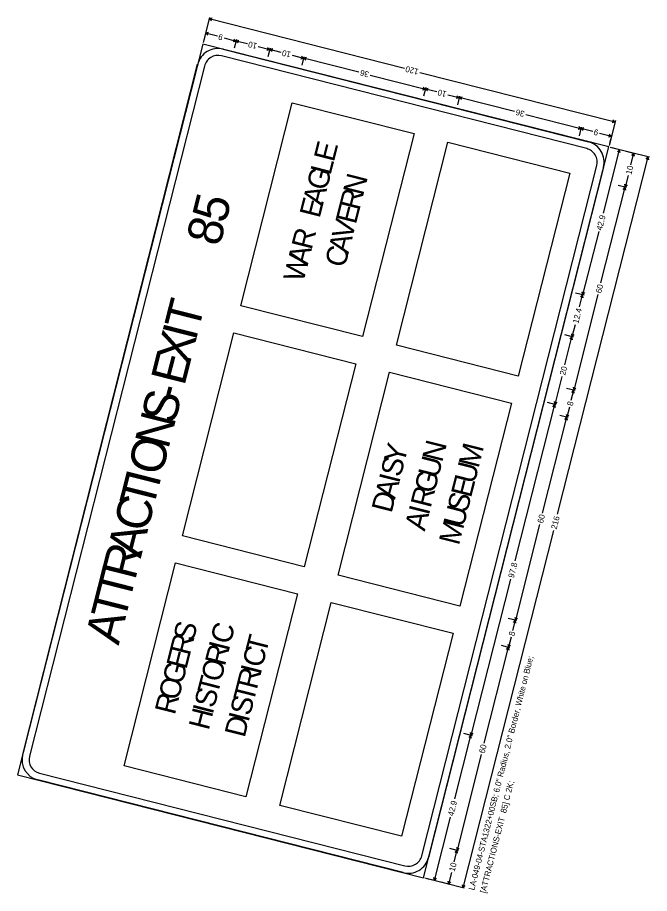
# Model space of a CAD drawing. Extents: x 670257 to 671518, y 737783 to 738188.
# Drawn here: x 670990.48 to 671016.9, y 737940.95 to 737977.55 of the extents above; entities that cross this region are included whole.
import ezdxf

# ---------------------------------------------------------------- set-up
doc = ezdxf.new("R2010")
doc.units = 0
doc.layers.add('R_SIGN', color=7, linetype='Continuous')

msp = doc.modelspace()

# ---------------------------------------------------------------- linework, layer by layer
at = {"layer": 'R_SIGN'}
for p, q in [((670998.509, 737977.55), (670998.244, 737976.503)), ((670998.615, 737977.517), (670998.494, 737977.49)), ((671006.654, 737975.421), (670998.494, 737977.49)), ((670998.587, 737977.41), (670998.494, 737977.49)), ((670998.357, 737976.952), (670998.266, 737976.593)), ((670998.463, 737976.918), (670998.342, 737976.892)), ((670998.836, 737976.767), (670998.342, 737976.892)), ((670998.436, 737976.811), (670998.342, 737976.892)), ((670999.12, 737976.695), (670999.615, 737976.569)), ((670999.494, 737976.543), (670999.615, 737976.569)), ((670999.521, 737976.65), (670999.615, 737976.569)), ((670999.63, 737976.629), (670999.539, 737976.27)), ((670999.735, 737976.596), (670999.615, 737976.569)), ((671000.095, 737976.447), (670999.615, 737976.569)), ((670999.708, 737976.489), (670999.615, 737976.569)), ((671000.547, 737976.333), (671001.028, 737976.211)), ((671000.908, 737976.184), (671001.028, 737976.211)), ((671000.935, 737976.291), (671001.028, 737976.211)), ((671001.043, 737976.271), (671000.952, 737975.912)), ((671001.149, 737976.237), (671001.028, 737976.211)), ((671001.509, 737976.089), (671001.028, 737976.211)), ((671001.122, 737976.13), (671001.028, 737976.211)), ((671001.961, 737975.974), (671002.442, 737975.852)), ((671002.321, 737975.826), (671002.442, 737975.852)), ((671002.348, 737975.933), (671002.442, 737975.852)), ((671002.457, 737975.912), (671002.366, 737975.553)), ((671002.562, 737975.879), (671002.442, 737975.852)), ((671004.748, 737975.267), (671002.442, 737975.852)), ((671002.535, 737975.772), (671002.442, 737975.852)), ((671005.224, 737975.146), (671007.531, 737974.562)), ((671007.297, 737975.257), (671015.457, 737973.188)), ((671007.41, 737974.535), (671007.531, 737974.562)), ((671007.437, 737974.642), (671007.531, 737974.562)), ((671007.546, 737974.621), (671007.455, 737974.262)), ((671007.651, 737974.588), (671007.531, 737974.562)), ((671008.011, 737974.44), (671007.531, 737974.562)), ((671007.624, 737974.481), (671007.531, 737974.562)), ((671008.463, 737974.325), (671008.944, 737974.203)), ((670999.818, 737965.508), (671001.969, 737973.99)), ((671001.969, 737973.99), (671007.058, 737972.699)), ((671008.824, 737974.177), (671008.944, 737974.203)), ((671008.851, 737974.284), (671008.944, 737974.203)), ((671008.959, 737974.263), (671008.868, 737973.904)), ((671009.065, 737974.229), (671008.944, 737974.203)), ((671011.25, 737973.618), (671008.944, 737974.203)), ((671009.038, 737974.122), (671008.944, 737974.203)), ((671011.727, 737973.497), (671014.033, 737972.912)), ((671015.472, 737973.248), (671015.207, 737972.201)), ((671015.364, 737973.269), (671015.457, 737973.188)), ((671013.912, 737972.886), (671014.033, 737972.912)), ((671013.94, 737972.993), (671014.033, 737972.912)), ((671014.048, 737972.972), (671013.957, 737972.613)), ((671014.048, 737972.972), (671013.957, 737972.613)), ((671014.154, 737972.939), (671014.033, 737972.912)), ((671014.527, 737972.787), (671014.033, 737972.912)), ((671014.126, 737972.832), (671014.033, 737972.912)), ((671015.336, 737973.162), (671015.457, 737973.188)), ((671007.058, 737972.699), (671004.907, 737964.218)), ((671014.811, 737972.715), (671015.305, 737972.59)), ((671015.185, 737972.563), (671015.305, 737972.59)), ((671015.212, 737972.67), (671015.305, 737972.59)), ((671015.32, 737972.65), (671015.229, 737972.291)), ((671006.321, 737963.859), (671008.472, 737972.341)), ((671008.472, 737972.341), (671013.561, 737971.05)), ((671016.897, 737971.709), (671015.251, 737972.126)), ((671014.969, 737969.382), (671015.64, 737972.027)), ((671015.7, 737972.012), (671015.341, 737972.103)), ((671015.56, 737971.934), (671015.64, 737972.027)), ((671015.667, 737971.907), (671015.64, 737972.027)), ((671016.298, 737971.86), (671015.939, 737971.951)), ((671016.116, 737971.395), (671016.238, 737971.876)), ((671016.158, 737971.782), (671016.238, 737971.876)), ((671016.265, 737971.755), (671016.238, 737971.876)), ((671013.05, 737956.794), (671016.837, 737971.724)), ((671016.756, 737971.63), (671016.837, 737971.724)), ((671016.863, 737971.603), (671016.837, 737971.724)), ((671013.561, 737971.05), (671011.41, 737962.569)), ((671016.002, 737970.943), (671015.88, 737970.462)), ((671014.865, 737966.459), (671015.88, 737970.462)), ((671015.94, 737970.447), (671015.581, 737970.538)), ((671015.94, 737970.447), (671015.581, 737970.538)), ((671015.799, 737970.368), (671015.88, 737970.462)), ((671015.854, 737970.583), (671015.88, 737970.462)), ((671015.961, 737970.555), (671015.88, 737970.462)), ((671015.906, 737970.341), (671015.88, 737970.462)), ((671014.773, 737968.608), (671014.102, 737965.963)), ((671014.744, 737965.983), (671013.729, 737961.98)), ((671014.162, 737965.948), (671013.803, 737966.039)), ((671014.162, 737965.948), (671013.803, 737966.039)), ((671013.973, 737965.456), (671014.102, 737965.963)), ((671014.022, 737965.87), (671014.102, 737965.963)), ((671014.076, 737966.084), (671014.102, 737965.963)), ((671014.183, 737966.056), (671014.102, 737965.963)), ((671014.129, 737965.842), (671014.102, 737965.963)), ((671004.907, 737964.218), (670999.818, 737965.508)), ((671013.786, 737964.717), (671013.658, 737964.21)), ((670997.38, 737955.896), (670999.531, 737964.378)), ((670999.531, 737964.378), (671004.62, 737963.087)), ((671013.717, 737964.195), (671013.358, 737964.286)), ((671013.36, 737963.036), (671013.658, 737964.21)), ((671013.577, 737964.117), (671013.658, 737964.21)), ((671013.631, 737964.331), (671013.658, 737964.21)), ((671013.738, 737964.304), (671013.658, 737964.21)), ((671013.684, 737964.09), (671013.658, 737964.21)), ((671011.41, 737962.569), (671006.321, 737963.859)), ((671004.62, 737963.087), (671002.469, 737954.606)), ((671003.883, 737954.247), (671006.034, 737962.728)), ((671006.034, 737962.728), (671011.123, 737961.438)), ((671013.238, 737962.558), (671012.94, 737961.383)), ((671013.789, 737961.965), (671013.43, 737962.056)), ((671013.621, 737961.558), (671013.729, 737961.98)), ((671013.648, 737961.887), (671013.729, 737961.98)), ((671013.702, 737962.101), (671013.729, 737961.98)), ((671013.809, 737962.074), (671013.729, 737961.98)), ((671013.755, 737961.86), (671013.729, 737961.98)), ((671012.914, 737961.504), (671012.94, 737961.383)), ((671011.123, 737961.438), (671008.972, 737952.956)), ((671011.284, 737954.852), (671012.94, 737961.383)), ((671013, 737961.368), (671012.641, 737961.459)), ((671012.86, 737961.29), (671012.94, 737961.383)), ((671013.021, 737961.476), (671012.94, 737961.383)), ((671012.967, 737961.262), (671012.94, 737961.383)), ((671013.549, 737961.273), (671013.442, 737960.85)), ((671012.427, 737956.847), (671013.442, 737960.85)), ((671013.502, 737960.834), (671013.143, 737960.925)), ((671013.361, 737960.756), (671013.442, 737960.85)), ((671013.416, 737960.97), (671013.442, 737960.85)), ((671013.523, 737960.943), (671013.442, 737960.85)), ((671013.468, 737960.729), (671013.442, 737960.85)), ((671012.879, 737956.12), (671009.093, 737941.19)), ((671012.306, 737956.371), (671011.291, 737952.368)), ((671002.469, 737954.606), (670997.38, 737955.896)), ((670994.942, 737946.284), (670997.094, 737954.765)), ((670997.094, 737954.765), (671002.182, 737953.475)), ((671008.972, 737952.956), (671003.883, 737954.247)), ((671011.091, 737954.089), (671009.434, 737947.558)), ((671002.182, 737953.475), (671000.031, 737944.993)), ((671001.445, 737944.635), (671003.596, 737953.116)), ((671003.596, 737953.116), (671008.685, 737951.825)), ((671011.351, 737952.353), (671010.992, 737952.444)), ((671011.184, 737951.945), (671011.291, 737952.368)), ((671011.21, 737952.275), (671011.291, 737952.368)), ((671011.265, 737952.489), (671011.291, 737952.368)), ((671011.372, 737952.462), (671011.291, 737952.368)), ((671011.317, 737952.248), (671011.291, 737952.368)), ((671008.685, 737951.825), (671006.534, 737943.344)), ((671011.111, 737951.66), (671011.004, 737951.237)), ((671011.064, 737951.222), (671010.705, 737951.313)), ((671010.978, 737951.358), (671011.004, 737951.237)), ((671011.085, 737951.331), (671011.004, 737951.237)), ((671009.989, 737947.234), (671011.004, 737951.237)), ((671010.923, 737951.144), (671011.004, 737951.237)), ((671011.03, 737951.117), (671011.004, 737951.237)), ((671009.494, 737947.543), (671009.135, 737947.634)), ((671009.408, 737947.679), (671009.434, 737947.558)), ((671009.515, 737947.652), (671009.434, 737947.558)), ((671008.763, 737944.913), (671009.434, 737947.558)), ((671009.354, 737947.465), (671009.434, 737947.558)), ((671009.461, 737947.438), (671009.434, 737947.558)), ((671009.868, 737946.759), (671008.853, 737942.756)), ((671000.031, 737944.993), (670994.942, 737946.284)), ((671006.534, 737943.344), (671001.445, 737944.635)), ((671008.567, 737944.139), (671007.896, 737941.494)), ((671008.827, 737942.876), (671008.853, 737942.756)), ((671008.934, 737942.849), (671008.853, 737942.756)), ((671008.913, 737942.741), (671008.554, 737942.832)), ((671008.731, 737942.275), (671008.853, 737942.756)), ((671008.772, 737942.662), (671008.853, 737942.756)), ((671008.879, 737942.635), (671008.853, 737942.756)), ((671008.616, 737941.823), (671008.494, 737941.342)), ((671009.153, 737941.175), (671007.507, 737941.593)), ((671007.956, 737941.479), (671007.597, 737941.57)), ((671007.87, 737941.615), (671007.896, 737941.494)), ((671007.977, 737941.587), (671007.896, 737941.494)), ((671008.554, 737941.327), (671008.195, 737941.418)), ((671008.468, 737941.463), (671008.494, 737941.342)), ((671008.575, 737941.436), (671008.494, 737941.342)), ((671009.066, 737941.311), (671009.093, 737941.19)), ((671009.173, 737941.284), (671009.093, 737941.19))]:
    msp.add_line(p, q, dxfattribs=at)
for points in [[(671007.448, 737941.608), (671015.191, 737972.141), (670998.229, 737976.443), (670990.485, 737945.91), (671007.448, 737941.608), (671007.448, 737941.608)], [(670999.077, 737976.228), (671014.343, 737972.356)], [(671014.272, 737972.073), (670999.005, 737975.945)], [(670990.7, 737946.758), (670998.013, 737975.595)], [(670998.296, 737975.523), (670990.982, 737946.686)], [(671007.38, 737942.528), (671014.694, 737971.365)], [(671014.976, 737971.293), (671007.663, 737942.456)], [(670991.404, 737945.978), (671006.671, 737942.106)], [(671006.599, 737941.823), (670991.333, 737945.695)]]:
    msp.add_lwpolyline(points, dxfattribs=at)
for centre, radius, start, end in [((670998.862, 737975.38), 0.875, 75.7686, 165.7688), ((670998.862, 737975.38), 0.583, 75.7686, 165.7688), ((671014.128, 737971.508), 0.875, 345.7686, 75.7688), ((671014.128, 737971.508), 0.583, 345.7686, 75.7688), ((670991.548, 737946.543), 0.875, 165.7688, 255.7684), ((670991.548, 737946.543), 0.583, 165.7688, 255.7684), ((671006.814, 737942.671), 0.583, 255.7684, 345.7686), ((671006.814, 737942.671), 0.875, 255.7684, 345.7686)]:
    msp.add_arc(centre, radius, start, end, dxfattribs=at)

# ---------------------------------------------------------------- texts
for s, height, rotation, p in [('9', 0.247, 165.7688, (670999.091, 737976.829)), ('10', 0.2469, 165.7688, (671000.518, 737976.468)), ('10', 0.2469, 165.7688, (671001.931, 737976.109)), ('120', 0.2469, 165.7688, (671007.268, 737975.392)), ('36', 0.2469, 165.7688, (671005.195, 737975.281)), ('10', 0.2469, 165.7688, (671008.434, 737974.46)), ('36', 0.2469, 165.7688, (671011.697, 737973.632)), ('9', 0.247, 165.7688, (671014.782, 737972.85)), ('E', 0.875, 75.7686, (671003.703, 737971.483)), ('L', 0.875, 75.7686, (671003.563, 737970.932)), ('G', 0.875, 75.7686, (671003.4, 737970.287)), ('N', 0.875, 75.7686, (671004.926, 737970.076)), ('10', 0.2469, 75.7686, (671016.137, 737970.972)), ('A', 0.875, 75.7686, (671003.236, 737969.643)), ('R', 0.875, 75.7686, (671004.769, 737969.457)), ('5', 1.458, 75.7686, (670999.176, 737968.906)), ('E', 0.875, 75.7686, (671003.107, 737969.134)), ('E', 0.875, 75.7686, (671004.623, 737968.88)), ('8', 1.458, 75.7686, (670998.932, 737967.945)), ('V', 0.875, 75.7686, (671004.459, 737968.236)), ('42.9', 0.2469, 75.7686, (671014.908, 737968.638)), ('R', 0.875, 75.7686, (671002.772, 737967.811)), ('A', 0.875, 75.7686, (671004.309, 737967.642)), ('W', 0.875, 75.7686, (671002.428, 737966.454)), ('A', 0.875, 75.7686, (671002.604, 737967.149)), ('C', 0.875, 75.7686, (671004.162, 737967.065)), ('60', 0.2469, 75.7686, (671014.879, 737966.013)), ('T', 1.458, 75.7686, (670998.032, 737964.397)), ('12.4', 0.2469, 75.7686, (671013.921, 737964.747)), ('X', 1.458, 75.7686, (670997.67, 737962.969)), ('I', 1.458, 75.7686, (670997.931, 737964.001)), ('E', 1.458, 75.7686, (670997.455, 737962.121)), ('20', 0.2469, 75.7686, (671013.373, 737962.587)), ('S', 1.458, 75.7686, (670997.046, 737960.51)), ('-', 1.458, 75.7686, (670997.279, 737961.428)), ('8', 0.247, 75.7686, (671013.684, 737961.302)), ('N', 1.458, 75.7686, (670996.784, 737959.478)), ('O', 1.458, 75.7686, (670996.501, 737958.361)), ('Y', 0.875, 75.7686, (671006.634, 737958.866)), ('N', 0.875, 75.7686, (671008.231, 737958.935)), ('M', 0.875, 75.7686, (671009.749, 737958.69)), ('S', 0.875, 75.7686, (671006.494, 737958.315)), ('U', 0.875, 75.7686, (671008.063, 737958.273)), ('U', 0.875, 75.7686, (671009.581, 737958.028)), ('I', 1.458, 75.7686, (670996.379, 737957.88)), ('G', 0.875, 75.7686, (671007.9, 737957.629)), ('T', 1.458, 75.7686, (670996.146, 737956.961)), ('I', 0.875, 75.7686, (671006.428, 737958.052)), ('E', 0.875, 75.7686, (671009.435, 737957.452)), ('A', 0.875, 75.7686, (671006.26, 737957.39)), ('R', 0.875, 75.7686, (671007.747, 737957.027)), ('C', 1.458, 75.7686, (670995.902, 737956)), ('D', 0.875, 75.7686, (671006.114, 737956.814)), ('S', 0.875, 75.7686, (671009.278, 737956.833)), ('I', 0.875, 75.7686, (671007.67, 737956.721)), ('U', 0.875, 75.7686, (671009.121, 737956.213)), ('A', 0.875, 75.7686, (671007.502, 737956.06)), ('60', 0.2469, 75.7686, (671012.441, 737956.401)), ('M', 0.875, 75.7686, (671008.931, 737955.467)), ('216', 0.2469, 75.7686, (671013.014, 737956.15)), ('A', 1.458, 75.7686, (670995.63, 737954.926)), ('R', 1.458, 75.7686, (670995.397, 737954.007)), ('T', 1.458, 75.7686, (670995.164, 737953.088)), ('97.8', 0.2469, 75.7686, (671011.225, 737954.118)), ('T', 1.458, 75.7686, (670994.959, 737952.283)), ('A', 1.458, 75.7686, (670994.708, 737951.293)), ('S', 0.875, 75.7686, (670997.829, 737951.437)), ('C', 0.875, 75.7686, (670999.381, 737951.328)), ('R', 0.875, 75.7686, (670997.683, 737950.861)), ('T', 0.875, 75.7686, (671000.859, 737950.926)), ('8', 0.247, 75.7686, (671011.246, 737951.69)), ('R', 0.875, 75.7686, (670999.151, 737950.421)), ('I', 0.875, 75.7686, (670999.308, 737951.04)), ('C', 0.875, 75.7686, (671000.713, 737950.349)), ('E', 0.875, 75.7686, (670997.537, 737950.284)), ('G', 0.875, 75.7686, (670997.373, 737949.639)), ('O', 0.875, 75.7686, (670998.981, 737949.75)), ('LA-049-04-STA1322+00SB; 6.0" Radius, 2.0" Border, White on Blue; ', 0.24688, 75.7686, (671009.571, 737941.069)), ('R', 0.875, 75.7686, (671000.483, 737949.442)), ('I', 0.875, 75.7686, (671000.64, 737950.061)), ('O', 0.875, 75.7686, (670997.208, 737948.986)), ('T', 0.875, 75.7686, (670998.846, 737949.216)), ('S', 0.875, 75.7686, (670998.706, 737948.665)), ('T', 0.875, 75.7686, (671000.343, 737948.891)), ('R', 0.875, 75.7686, (670997.055, 737948.384)), ('S', 0.875, 75.7686, (671000.203, 737948.339)), ('I', 0.875, 75.7686, (670998.639, 737948.402)), ('H', 0.875, 75.7686, (670998.471, 737947.74)), ('D', 0.875, 75.7686, (670999.973, 737947.432)), ('I', 0.875, 75.7686, (671000.136, 737948.076)), ('60', 0.2469, 75.7686, (671010.003, 737946.788)), ('[ATTRACTIONS-EXIT  85] C 2K; ', 0.24688, 75.7686, (671010.05, 737940.948)), ('42.9', 0.2469, 75.7686, (671008.702, 737944.169)), ('10', 0.2469, 75.7686, (671008.751, 737941.853))]:
    msp.add_text(s, height=height, rotation=rotation, dxfattribs=at).set_placement(p)

doc.saveas('drawing.dxf')
